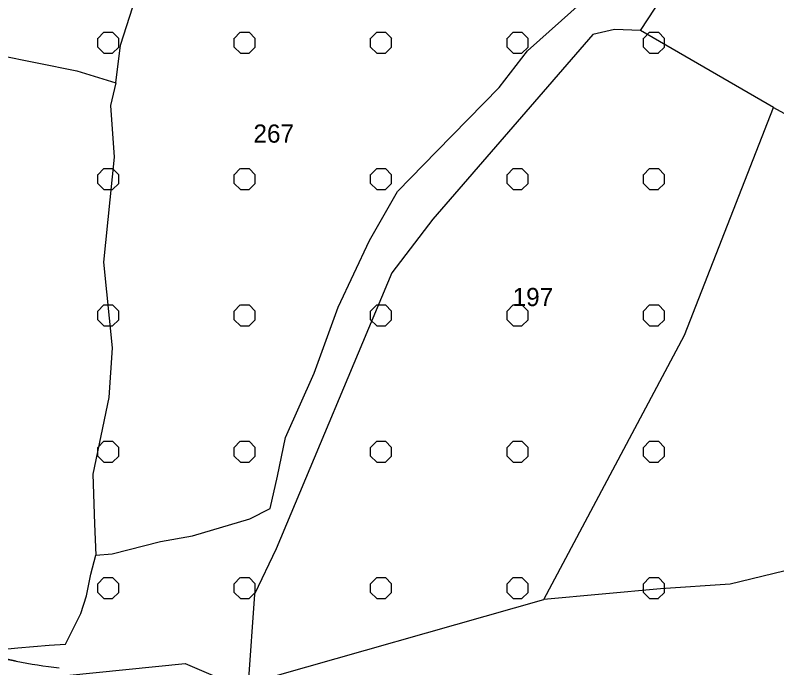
# Model space of a CAD drawing. Extents: x 410727 to 412947, y 4463506 to 4466382.
# Drawn here: x 411364.1 to 411531.6, y 4466009.6 to 4466153.2 of the extents above; entities that cross this region are included whole.
import ezdxf

# ---------------------------------------------------------------- set-up
doc = ezdxf.new("R2010")
doc.units = 0
for name, color, linetype in [('ADAKENARI', 7, 'Continuous'), ('KDS_PARSEL_NO', 7, 'Continuous'), ('KDS_PL', 7, 'Continuous'), ('PL_KA_TARIM_OZEL', 7, 'Continuous'), ('TR_OZELMAHSUL', 7, 'Continuous'), ('Yerlesime_uygunluk_sınırı', 7, 'Continuous')]:
    doc.layers.add(name, color=color, linetype=linetype)

msp = doc.modelspace()

# ---------------------------------------------------------------- linework, layer by layer
at = {"layer": 'ADAKENARI'}
msp.add_line((411364.32, 4466011.06), (411345.29, 4466015.03), dxfattribs=at)
msp.add_arc((411383.75, 4466104.05), 95, 258.2027, 263.991, dxfattribs=at)
msp.add_arc((411383.75, 4466104.05), 95, 258.2027, 263.991, dxfattribs=at)
at = {"layer": 'KDS_PL'}
for p, q in [((411501.66, 4466149.81), (411529.62, 4466192.66)), ((411387.27, 4466146.55), (411391.26, 4466158.85)), ((411476.81, 4466145.32), (411489.03, 4466156.27)), ((411495.94, 4466150.03), (411491.12, 4466148.94)), ((411501.66, 4466149.81), (411495.94, 4466150.03)), ((411530.91, 4466132.84), (411501.66, 4466149.81)), ((411343.47, 4466147.88), (411377.65, 4466140.9)), ((411491.12, 4466148.94), (411455.97, 4466108.25)), ((411386.28, 4466138.24), (411387.27, 4466146.55)), ((411470.53, 4466137.26), (411476.81, 4466145.32)), ((411377.65, 4466140.9), (411386.28, 4466138.24)), ((411386.28, 4466138.24), (411385.09, 4466133.3)), ((411456.86, 4466123.24), (411470.53, 4466137.26)), ((411385.09, 4466133.3), (411385.87, 4466121.93)), ((411511.28, 4466082.72), (411530.91, 4466132.84)), ((411530.91, 4466132.84), (411568.94, 4466111.75)), ((411448.18, 4466114.38), (411456.86, 4466123.24)), ((411385.87, 4466121.93), (411383.52, 4466098.81)), ((411442.07, 4466103.58), (411448.18, 4466114.38)), ((411455.97, 4466108.25), (411446.94, 4466096.5)), ((411435.15, 4466088.92), (411442.07, 4466103.58)), ((411383.52, 4466098.81), (411385.48, 4466080)), ((411446.94, 4466096.5), (411421.53, 4466035.78)), ((411429.85, 4466074.42), (411435.15, 4466088.92)), ((411480.34, 4466024.59), (411511.28, 4466082.72)), ((411385.48, 4466080), (411384.69, 4466069.03)), ((411423.58, 4466060.24), (411429.85, 4466074.42)), ((411384.69, 4466069.03), (411381.17, 4466052.18)), ((411421.81, 4466051.7), (411423.58, 4466060.24)), ((411381.17, 4466052.18), (411381.57, 4466041.21)), ((411420.2, 4466044.61), (411421.81, 4466051.7)), ((411415.69, 4466042.35), (411420.2, 4466044.61)), ((411403.15, 4466038.64), (411415.69, 4466042.35)), ((411381.57, 4466041.21), (411381.84, 4466034.32)), ((411385.46, 4466034.61), (411396.07, 4466037.35)), ((411396.07, 4466037.35), (411403.15, 4466038.64)), ((411421.53, 4466035.78), (411416.72, 4466025.78)), ((411380.77, 4466030.15), (411381.84, 4466034.32)), ((411381.84, 4466034.32), (411385.46, 4466034.61)), ((411544.12, 4466033.5), (411521.38, 4466028)), ((411379.8, 4466025.41), (411380.77, 4466030.15)), ((411521.38, 4466028), (411506.06, 4466026.97)), ((411416.72, 4466025.78), (411415.34, 4466006.12)), ((411506.06, 4466026.97), (411480.34, 4466024.59)), ((411378.55, 4466021.53), (411379.8, 4466025.41)), ((411415.34, 4466006.12), (411480.34, 4466024.59)), ((411375.16, 4466014.75), (411378.55, 4466021.53)), ((411352.82, 4466012.81), (411364.72, 4466013.97)), ((411364.72, 4466013.97), (411371.59, 4466014.55)), ((411371.59, 4466014.55), (411375.16, 4466014.75))]:
    msp.add_line(p, q, dxfattribs=at)
at = {"layer": 'PL_KA_TARIM_OZEL'}
msp.add_lwpolyline([(411345.29, 4466015.03), (411364.32, 4466011.06)], dxfattribs=at)
msp.add_arc((411383.75, 4466104.05), 95, 258.2027, 263.991, dxfattribs=at)
at = {"layer": 'TR_OZELMAHSUL'}
for p, q in [((411382.28, 4466148.06), (411383.64, 4466149.42)), ((411383.64, 4466149.42), (411385.56, 4466149.42)), ((411386.92, 4466148.06), (411385.56, 4466149.41)), ((411412.28, 4466148.06), (411413.63, 4466149.42)), ((411413.64, 4466149.42), (411415.56, 4466149.42)), ((411416.92, 4466148.06), (411415.56, 4466149.41)), ((411442.28, 4466148.06), (411443.63, 4466149.41)), ((411443.64, 4466149.42), (411445.56, 4466149.42)), ((411446.92, 4466148.06), (411445.56, 4466149.41)), ((411472.28, 4466148.06), (411473.63, 4466149.41)), ((411473.64, 4466149.42), (411475.56, 4466149.42)), ((411476.92, 4466148.06), (411475.56, 4466149.41)), ((411502.28, 4466148.06), (411503.63, 4466149.41)), ((411503.64, 4466149.42), (411505.56, 4466149.42)), ((411506.91, 4466148.06), (411505.56, 4466149.41)), ((411382.29, 4466146.15), (411382.29, 4466148.07)), ((411386.91, 4466146.15), (411386.91, 4466148.07)), ((411412.29, 4466146.15), (411412.29, 4466148.07)), ((411416.91, 4466146.15), (411416.91, 4466148.07)), ((411442.29, 4466146.15), (411442.29, 4466148.07)), ((411446.91, 4466146.15), (411446.91, 4466148.07)), ((411472.29, 4466146.15), (411472.29, 4466148.07)), ((411476.91, 4466146.15), (411476.91, 4466148.07)), ((411502.29, 4466146.15), (411502.29, 4466148.07)), ((411506.91, 4466146.15), (411506.91, 4466148.07)), ((411383.65, 4466144.79), (411382.29, 4466146.14)), ((411385.55, 4466144.79), (411386.91, 4466146.15)), ((411413.65, 4466144.79), (411412.29, 4466146.14)), ((411415.55, 4466144.79), (411416.9, 4466146.15)), ((411443.65, 4466144.79), (411442.29, 4466146.14)), ((411445.55, 4466144.79), (411446.9, 4466146.14)), ((411473.65, 4466144.79), (411472.29, 4466146.14)), ((411475.55, 4466144.79), (411476.9, 4466146.14)), ((411503.64, 4466144.79), (411502.29, 4466146.14)), ((411505.55, 4466144.79), (411506.9, 4466146.14)), ((411383.64, 4466144.8), (411385.56, 4466144.8)), ((411413.64, 4466144.8), (411415.56, 4466144.8)), ((411443.64, 4466144.8), (411445.56, 4466144.8)), ((411473.64, 4466144.8), (411475.56, 4466144.8)), ((411503.64, 4466144.8), (411505.56, 4466144.8)), ((411382.28, 4466118.06), (411383.64, 4466119.42)), ((411383.64, 4466119.42), (411385.56, 4466119.42)), ((411386.92, 4466118.06), (411385.56, 4466119.42)), ((411412.28, 4466118.06), (411413.63, 4466119.42)), ((411413.64, 4466119.42), (411415.56, 4466119.42)), ((411416.92, 4466118.06), (411415.56, 4466119.42)), ((411442.28, 4466118.06), (411443.63, 4466119.41)), ((411443.64, 4466119.42), (411445.56, 4466119.42)), ((411446.91, 4466118.06), (411445.56, 4466119.42)), ((411472.28, 4466118.06), (411473.63, 4466119.41)), ((411473.64, 4466119.42), (411475.56, 4466119.42)), ((411476.91, 4466118.06), (411475.56, 4466119.42)), ((411502.28, 4466118.06), (411503.63, 4466119.41)), ((411503.64, 4466119.42), (411505.56, 4466119.42)), ((411506.91, 4466118.06), (411505.56, 4466119.42)), ((411382.29, 4466116.15), (411382.29, 4466118.07)), ((411386.91, 4466116.15), (411386.91, 4466118.07)), ((411412.29, 4466116.15), (411412.29, 4466118.07)), ((411416.91, 4466116.15), (411416.91, 4466118.07)), ((411442.29, 4466116.15), (411442.29, 4466118.07)), ((411446.91, 4466116.15), (411446.91, 4466118.07)), ((411472.29, 4466116.15), (411472.29, 4466118.07)), ((411476.91, 4466116.15), (411476.91, 4466118.07)), ((411502.29, 4466116.15), (411502.29, 4466118.07)), ((411506.91, 4466116.15), (411506.91, 4466118.07)), ((411383.65, 4466114.79), (411382.29, 4466116.15)), ((411385.55, 4466114.79), (411386.91, 4466116.15)), ((411413.65, 4466114.79), (411412.29, 4466116.15)), ((411415.55, 4466114.79), (411416.9, 4466116.15)), ((411443.64, 4466114.79), (411442.29, 4466116.15)), ((411445.55, 4466114.79), (411446.9, 4466116.14)), ((411473.64, 4466114.79), (411472.29, 4466116.15)), ((411475.55, 4466114.79), (411476.9, 4466116.14)), ((411503.64, 4466114.79), (411502.29, 4466116.15)), ((411505.55, 4466114.79), (411506.9, 4466116.14)), ((411383.64, 4466114.8), (411385.56, 4466114.8)), ((411413.64, 4466114.8), (411415.56, 4466114.8)), ((411443.64, 4466114.8), (411445.56, 4466114.8)), ((411473.64, 4466114.8), (411475.56, 4466114.8)), ((411503.64, 4466114.8), (411505.56, 4466114.8)), ((411382.28, 4466088.06), (411383.64, 4466089.42)), ((411383.64, 4466089.42), (411385.56, 4466089.42)), ((411386.91, 4466088.06), (411385.56, 4466089.42)), ((411412.28, 4466088.06), (411413.63, 4466089.42)), ((411413.64, 4466089.42), (411415.56, 4466089.42)), ((411416.91, 4466088.06), (411415.56, 4466089.42)), ((411442.28, 4466088.06), (411443.63, 4466089.41)), ((411443.64, 4466089.42), (411445.56, 4466089.42)), ((411446.91, 4466088.06), (411445.56, 4466089.42)), ((411472.28, 4466088.06), (411473.63, 4466089.41)), ((411473.64, 4466089.42), (411475.56, 4466089.42)), ((411476.91, 4466088.06), (411475.56, 4466089.42)), ((411502.28, 4466088.06), (411503.63, 4466089.41)), ((411503.64, 4466089.42), (411505.56, 4466089.42)), ((411506.91, 4466088.06), (411505.56, 4466089.42)), ((411382.29, 4466086.15), (411382.29, 4466088.07)), ((411386.91, 4466086.15), (411386.91, 4466088.07)), ((411412.29, 4466086.15), (411412.29, 4466088.07)), ((411416.91, 4466086.15), (411416.91, 4466088.07)), ((411442.29, 4466086.15), (411442.29, 4466088.07)), ((411446.91, 4466086.15), (411446.91, 4466088.07)), ((411472.29, 4466086.15), (411472.29, 4466088.07)), ((411476.91, 4466086.15), (411476.91, 4466088.07)), ((411502.29, 4466086.15), (411502.29, 4466088.07)), ((411506.91, 4466086.15), (411506.91, 4466088.07)), ((411383.64, 4466084.79), (411382.29, 4466086.15)), ((411385.55, 4466084.79), (411386.91, 4466086.15)), ((411413.64, 4466084.79), (411412.29, 4466086.15)), ((411415.55, 4466084.79), (411416.9, 4466086.15)), ((411443.64, 4466084.79), (411442.29, 4466086.15)), ((411445.55, 4466084.79), (411446.9, 4466086.14)), ((411473.64, 4466084.79), (411472.29, 4466086.15)), ((411475.55, 4466084.79), (411476.9, 4466086.14)), ((411503.64, 4466084.79), (411502.29, 4466086.15)), ((411505.55, 4466084.79), (411506.9, 4466086.14)), ((411383.64, 4466084.8), (411385.56, 4466084.8)), ((411413.64, 4466084.8), (411415.56, 4466084.8)), ((411443.64, 4466084.8), (411445.56, 4466084.8)), ((411473.64, 4466084.8), (411475.56, 4466084.8)), ((411503.64, 4466084.8), (411505.56, 4466084.8)), ((411382.28, 4466058.06), (411383.64, 4466059.42)), ((411383.64, 4466059.42), (411385.56, 4466059.42)), ((411386.91, 4466058.06), (411385.56, 4466059.42)), ((411412.28, 4466058.06), (411413.63, 4466059.42)), ((411413.64, 4466059.42), (411415.56, 4466059.42)), ((411416.91, 4466058.06), (411415.56, 4466059.42)), ((411442.28, 4466058.06), (411443.63, 4466059.42)), ((411443.64, 4466059.42), (411445.56, 4466059.42)), ((411446.91, 4466058.06), (411445.56, 4466059.42)), ((411472.28, 4466058.06), (411473.63, 4466059.41)), ((411473.64, 4466059.42), (411475.56, 4466059.42)), ((411476.91, 4466058.06), (411475.56, 4466059.42)), ((411502.28, 4466058.06), (411503.63, 4466059.41)), ((411503.64, 4466059.42), (411505.56, 4466059.42)), ((411506.91, 4466058.06), (411505.56, 4466059.42)), ((411382.29, 4466056.15), (411382.29, 4466058.07)), ((411386.91, 4466056.15), (411386.91, 4466058.07)), ((411412.29, 4466056.15), (411412.29, 4466058.07)), ((411416.91, 4466056.15), (411416.91, 4466058.07)), ((411442.29, 4466056.15), (411442.29, 4466058.07)), ((411446.91, 4466056.15), (411446.91, 4466058.07)), ((411472.29, 4466056.15), (411472.29, 4466058.07)), ((411476.91, 4466056.15), (411476.91, 4466058.07)), ((411502.29, 4466056.15), (411502.29, 4466058.07)), ((411506.91, 4466056.15), (411506.91, 4466058.07)), ((411383.64, 4466054.79), (411382.29, 4466056.15)), ((411385.55, 4466054.79), (411386.91, 4466056.15)), ((411413.64, 4466054.79), (411412.29, 4466056.15)), ((411415.55, 4466054.79), (411416.9, 4466056.15)), ((411443.64, 4466054.79), (411442.29, 4466056.15)), ((411445.55, 4466054.79), (411446.9, 4466056.15)), ((411473.64, 4466054.79), (411472.29, 4466056.15)), ((411475.55, 4466054.79), (411476.9, 4466056.14)), ((411503.64, 4466054.79), (411502.29, 4466056.15)), ((411505.55, 4466054.79), (411506.9, 4466056.14)), ((411383.64, 4466054.8), (411385.56, 4466054.8)), ((411413.64, 4466054.8), (411415.56, 4466054.8)), ((411443.64, 4466054.8), (411445.56, 4466054.8)), ((411473.64, 4466054.8), (411475.56, 4466054.8)), ((411503.64, 4466054.8), (411505.56, 4466054.8)), ((411382.28, 4466028.06), (411383.64, 4466029.42)), ((411383.64, 4466029.42), (411385.56, 4466029.42)), ((411386.91, 4466028.06), (411385.56, 4466029.42)), ((411412.28, 4466028.06), (411413.63, 4466029.42)), ((411413.64, 4466029.42), (411415.56, 4466029.42)), ((411416.91, 4466028.06), (411415.56, 4466029.42)), ((411442.28, 4466028.06), (411443.63, 4466029.42)), ((411443.64, 4466029.42), (411445.56, 4466029.42)), ((411446.91, 4466028.06), (411445.56, 4466029.42)), ((411472.28, 4466028.06), (411473.63, 4466029.41)), ((411473.64, 4466029.42), (411475.56, 4466029.42)), ((411476.91, 4466028.06), (411475.56, 4466029.42)), ((411502.28, 4466028.06), (411503.63, 4466029.41)), ((411503.64, 4466029.42), (411505.56, 4466029.42)), ((411506.91, 4466028.06), (411505.56, 4466029.42)), ((411382.29, 4466026.15), (411382.29, 4466028.07)), ((411386.91, 4466026.15), (411386.91, 4466028.07)), ((411412.29, 4466026.15), (411412.29, 4466028.07)), ((411416.91, 4466026.15), (411416.91, 4466028.07)), ((411442.29, 4466026.15), (411442.29, 4466028.07)), ((411446.91, 4466026.15), (411446.91, 4466028.07)), ((411472.29, 4466026.15), (411472.29, 4466028.07)), ((411476.91, 4466026.15), (411476.91, 4466028.07)), ((411502.29, 4466026.15), (411502.29, 4466028.07)), ((411506.91, 4466026.15), (411506.91, 4466028.07)), ((411383.64, 4466024.79), (411382.29, 4466026.15)), ((411385.55, 4466024.79), (411386.91, 4466026.15)), ((411413.64, 4466024.79), (411412.29, 4466026.15)), ((411415.55, 4466024.79), (411416.9, 4466026.15)), ((411443.64, 4466024.79), (411442.29, 4466026.15)), ((411445.55, 4466024.79), (411446.9, 4466026.15)), ((411473.64, 4466024.79), (411472.29, 4466026.15)), ((411475.55, 4466024.79), (411476.9, 4466026.14)), ((411503.64, 4466024.79), (411502.29, 4466026.15)), ((411505.55, 4466024.79), (411506.9, 4466026.14)), ((411383.64, 4466024.8), (411385.56, 4466024.8)), ((411413.64, 4466024.8), (411415.56, 4466024.8)), ((411443.64, 4466024.8), (411445.56, 4466024.8)), ((411473.64, 4466024.8), (411475.56, 4466024.8)), ((411503.64, 4466024.8), (411505.56, 4466024.8))]:
    msp.add_line(p, q, dxfattribs=at)
at = {"layer": 'Yerlesime_uygunluk_sınırı'}
msp.add_lwpolyline([(411367.59, 4466324.54), (411367.57, 4466324.45), (411365.4, 4466317.37), (411329.85, 4466256.4), (411327.98, 4466256.94), (411298.02, 4466265.64), (411235.39, 4466203.01), (411292.89, 4466117.8), (411249.96, 4466080.27), (411288.76, 4466053.15), (411335.49, 4466003.87), (411401.49, 4466010.55), (411454, 4465988), (411518.19, 4465927.25), (411576.49, 4465880.17), (411546.8, 4465853.02), (411462.76, 4465826.95), (411417.87, 4465818.6), (411360.95, 4465816.44), (411257.66, 4465822.32), (411198.74, 4465810.19), (411081.53, 4465694.24)], dxfattribs=at)

# ---------------------------------------------------------------- texts
at = {"layer": 'KDS_PARSEL_NO'}
for s, p in [('267', (411416.52, 4466125.11)), ('197', (411473.51, 4466089.15))]:
    msp.add_text(s, height=4, dxfattribs=at).set_placement(p)

doc.saveas('drawing.dxf')
